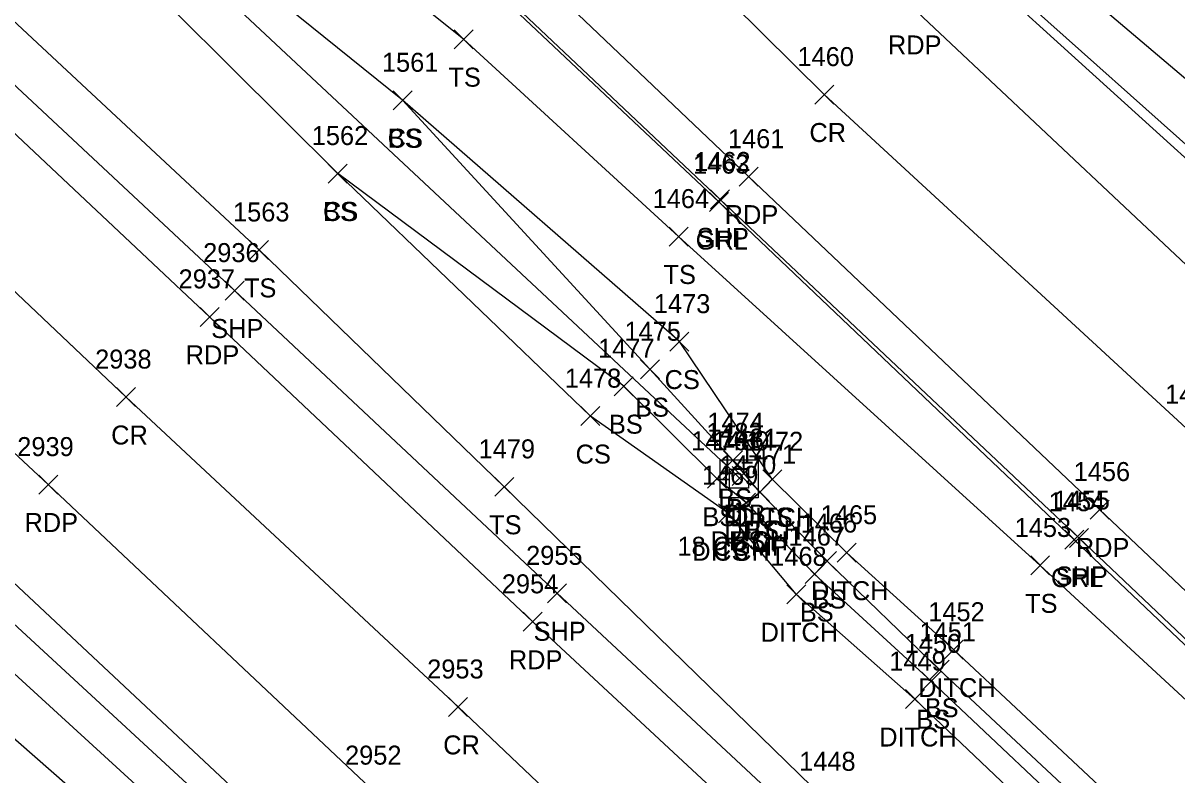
# Model space of a CAD drawing. Extents: x 1647574 to 1652703, y 212895 to 228670.
# Drawn here: x 1649239.7 to 1649361.4, y 226821.7 to 226900.9 of the extents above; entities that cross this region are included whole.
import ezdxf

# ---------------------------------------------------------------- set-up
doc = ezdxf.new("R2010")
doc.units = 0
for name, color, linetype in [('D_A', 7, 'Continuous'), ('D_C', 7, 'Continuous'), ('D_I', 7, 'Continuous'), ('D_TIC', 7, 'Continuous'), ('DCP', 7, 'Continuous'), ('DD', 7, 'Continuous'), ('DS', 7, 'Continuous'), ('L_A', 7, 'Continuous'), ('L_I', 7, 'Continuous'), ('L_TIC', 7, 'Continuous'), ('LELB', 7, 'Continuous'), ('P_A', 7, 'Continuous'), ('P_I', 7, 'Continuous'), ('P_TIC', 7, 'Continuous'), ('PET', 7, 'Continuous'), ('PRC', 7, 'Continuous'), ('PSP', 7, 'Continuous'), ('R_A', 7, 'Continuous'), ('R_I', 7, 'Continuous'), ('R_TIC', 7, 'Continuous'), ('RGR', 7, 'Continuous')]:
    doc.layers.add(name, color=color, linetype=linetype)

msp = doc.modelspace()

# ---------------------------------------------------------------- linework, layer by layer
at = {"layer": 'D_TIC'}
for points in [[(1649313.43, 226852.77), (1649315.43, 226854.77)], [(1649315.43, 226852.77), (1649313.43, 226854.77)], [(1649314.47, 226852.16), (1649316.47, 226854.16)], [(1649316.47, 226852.16), (1649314.47, 226854.16)], [(1649317.71, 226851.83), (1649319.71, 226853.83)], [(1649319.71, 226851.83), (1649317.71, 226853.83)], [(1649317.71, 226851.83), (1649319.71, 226853.83)], [(1649319.71, 226851.83), (1649317.71, 226853.83)], [(1649316.41, 226850.47), (1649318.41, 226852.47)], [(1649318.41, 226850.47), (1649316.41, 226852.47)], [(1649313.05, 226848.25), (1649315.05, 226850.25)], [(1649315.05, 226848.25), (1649313.05, 226850.25)], [(1649314.96, 226849.35), (1649316.96, 226851.35)], [(1649316.96, 226849.35), (1649314.96, 226851.35)], [(1649325.56, 226844.09), (1649327.56, 226846.09)], [(1649327.56, 226844.09), (1649325.56, 226846.09)], [(1649320.24, 226839.71), (1649322.24, 226841.71)], [(1649322.24, 226839.71), (1649320.24, 226841.71)], [(1649336.85, 226833.87), (1649338.85, 226835.87)], [(1649338.85, 226833.87), (1649336.85, 226835.87)], [(1649332.75, 226828.67), (1649334.75, 226830.67)], [(1649334.75, 226828.67), (1649332.75, 226830.67)]]:
    msp.add_lwpolyline(points, dxfattribs=at)
at = {"layer": 'DCP'}
msp.add_lwpolyline([(1649314.43, 226853.77), (1649218.25, 226943.62)], dxfattribs=at)
at = {"layer": 'DD'}
for points in [[(1649433.71, 226734.92), (1649406.56, 226760.63), (1649369.44, 226795.75), (1649333.75, 226829.67), (1649321.24, 226840.71), (1649314.05, 226849.25), (1649315.96, 226850.35), (1649317.41, 226851.47), (1649318.71, 226852.83)], [(1649433.71, 226734.92), (1649435.72, 226737.04), (1649437.39, 226738.45), (1649438.68, 226740.23), (1649411.63, 226765.29), (1649374.97, 226800.14), (1649337.85, 226834.87), (1649326.56, 226845.09), (1649318.71, 226852.83)]]:
    msp.add_lwpolyline(points, dxfattribs=at)
at = {"layer": 'DS'}
for p, q in [((1649313.21, 226854.88), (1649317.21, 226854.88)), ((1649313.21, 226850.88), (1649313.21, 226854.88)), ((1649317.21, 226854.88), (1649317.21, 226850.88)), ((1649314.21, 226851.88), (1649314.21, 226853.88)), ((1649314.21, 226853.88), (1649316.21, 226853.88)), ((1649315.21, 226852.88), (1649315.21, 226852.88)), ((1649315.21, 226852.88), (1649315.21, 226852.88)), ((1649316.21, 226853.88), (1649316.21, 226851.88)), ((1649316.21, 226851.88), (1649314.21, 226851.88)), ((1649317.21, 226850.88), (1649313.21, 226850.88))]:
    msp.add_line(p, q, dxfattribs=at)
at = {"layer": 'L_TIC'}
for points in [[(1649285.16, 226898.19), (1649287.16, 226900.19)], [(1649287.16, 226898.19), (1649285.16, 226900.19)], [(1649278.73, 226891.76), (1649280.73, 226893.76)], [(1649280.73, 226891.76), (1649278.73, 226893.76)], [(1649278.73, 226891.76), (1649280.73, 226893.76)], [(1649280.73, 226891.76), (1649278.73, 226893.76)], [(1649271.9, 226884.04), (1649273.9, 226886.04)], [(1649273.9, 226884.04), (1649271.9, 226886.04)], [(1649271.9, 226884.04), (1649273.9, 226886.04)], [(1649273.9, 226884.04), (1649271.9, 226886.04)], [(1649307.84, 226877.4), (1649309.84, 226879.4)], [(1649309.84, 226877.4), (1649307.84, 226879.4)], [(1649263.6, 226875.99), (1649265.6, 226877.99)], [(1649265.6, 226875.99), (1649263.6, 226877.99)], [(1649307.92, 226866.33), (1649309.92, 226868.33)], [(1649309.92, 226866.33), (1649307.92, 226868.33)], [(1649304.82, 226863.42), (1649306.82, 226865.42)], [(1649306.82, 226863.42), (1649304.82, 226865.42)], [(1649302.05, 226861.63), (1649304.05, 226863.63)], [(1649304.05, 226861.63), (1649302.05, 226863.63)], [(1649298.54, 226858.48), (1649300.54, 226860.48)], [(1649300.54, 226858.48), (1649298.54, 226860.48)], [(1649313.57, 226853.84), (1649315.57, 226855.84)], [(1649315.57, 226853.84), (1649313.57, 226855.84)], [(1649289.45, 226851.03), (1649291.45, 226853.03)], [(1649291.45, 226851.03), (1649289.45, 226853.03)], [(1649311.9, 226851.88), (1649313.9, 226853.88)], [(1649313.9, 226851.88), (1649311.9, 226853.88)], [(1649317.71, 226851.83), (1649319.71, 226853.83)], [(1649319.71, 226851.83), (1649317.71, 226853.83)], [(1649316.41, 226850.47), (1649318.41, 226852.47)], [(1649318.41, 226850.47), (1649316.41, 226852.47)], [(1649313.05, 226848.25), (1649315.05, 226850.25)], [(1649315.05, 226848.25), (1649313.05, 226850.25)], [(1649314.96, 226849.35), (1649316.96, 226851.35)], [(1649316.96, 226849.35), (1649314.96, 226851.35)], [(1649323.5, 226843.21), (1649325.5, 226845.21)], [(1649325.5, 226843.21), (1649323.5, 226845.21)], [(1649345.96, 226842.75), (1649347.96, 226844.75)], [(1649347.96, 226842.75), (1649345.96, 226844.75)], [(1649322.17, 226841.84), (1649324.17, 226843.84)], [(1649324.17, 226841.84), (1649322.17, 226843.84)], [(1649335.35, 226831.76), (1649337.35, 226833.76)], [(1649337.35, 226831.76), (1649335.35, 226833.76)], [(1649334.46, 226830.54), (1649336.46, 226832.54)], [(1649336.46, 226830.54), (1649334.46, 226832.54)]]:
    msp.add_lwpolyline(points, dxfattribs=at)
at = {"layer": 'LELB'}
for points in [[(1649050.36, 227022.26), (1649054.5, 227019.16), (1649077.5, 226992.81), (1649097.35, 226965.43), (1649118.34, 226949.96), (1649138.54, 226931.84), (1649168.25, 226903.68), (1649199.09, 226875.04), (1649233.63, 226842.31), (1649267.99, 226810.62), (1649300.85, 226778.49), (1649342.51, 226739.65), (1649376.73, 226707.3), (1649405.44, 226679.92), (1649436.03, 226650.7), (1649471.83, 226617.33), (1649509.36, 226581.5), (1649541.59, 226550.78), (1649576.43, 226518.4), (1649614.41, 226482.98)], [(1649601.72, 226556.3), (1649565.56, 226590.44), (1649531.93, 226623.52), (1649496.55, 226657.42), (1649463.01, 226688.13), (1649429.09, 226720.61), (1649397.93, 226750.55), (1649357.87, 226787.13), (1649324.24, 226819.11), (1649290.45, 226852.03), (1649264.6, 226876.99), (1649236.49, 226903.17), (1649212.26, 226932.02), (1649172.55, 226966.26), (1649148.69, 226987.13), (1649125.3, 227007.74), (1649116.81, 227012.43), (1649123.68, 227011.79), (1649139.12, 227006.12), (1649163.74, 226998.25), (1649180.85, 226995.42), (1649185.97, 226996.02), (1649188.1, 226997.43)], [(1649611.68, 226660.43), (1649573.8, 226694.76), (1649539.29, 226728.48), (1649506.26, 226759.21), (1649471.69, 226791.64), (1649437.47, 226825.67), (1649400.06, 226860.66), (1649373.97, 226885.13), (1649343.06, 226911.31), (1649307.79, 226942.26), (1649266.92, 226975.01), (1649262.13, 226979.91), (1649252.93, 226990.96)], [(1649593.12, 226613.01), (1649554.76, 226645.44), (1649523.05, 226677.15), (1649485.11, 226713.45), (1649453.02, 226743.38), (1649420.61, 226775.73), (1649384.19, 226809.44), (1649346.96, 226843.75), (1649308.84, 226878.4), (1649286.16, 226899.19), (1649254.43, 226924.59), (1649231.46, 226951.13), (1649215.58, 226955.64), (1649208.66, 226952.13), (1649203.07, 226945.74)], [(1649699.67, 226481.91), (1649679.45, 226501.99), (1649645.41, 226536.66), (1649612.61, 226568.57), (1649578.32, 226600.99), (1649543.98, 226632.95), (1649509.04, 226666.44), (1649473.07, 226698.81), (1649440.27, 226731.3), (1649435.72, 226737.04), (1649408.87, 226762.28), (1649371.65, 226797.42), (1649335.46, 226831.54), (1649323.17, 226842.84), (1649315.96, 226850.35), (1649312.9, 226852.88), (1649303.05, 226862.63), (1649272.9, 226885.04), (1649244.53, 226913.23), (1649219.14, 226937.73), (1649217.77, 226942.22), (1649215.75, 226944.46), (1649217.78, 226946.35), (1649219.53, 226943.85)], [(1649110.63, 226944.12), (1649132.81, 226926.76), (1649161.39, 226897.64), (1649168.83, 226891.36), (1649194.67, 226869.66), (1649227.44, 226835.45), (1649262.79, 226804.48), (1649294.65, 226771.03), (1649336.54, 226732.41), (1649369.74, 226699.93), (1649399.39, 226672.85), (1649429.85, 226642.79), (1649464.73, 226609.99), (1649502.63, 226572.81), (1649535.56, 226543.81), (1649570.19, 226510.51), (1649608.23, 226476.35)], [(1649699.67, 226481.91), (1649706.82, 226489.3), (1649683.4, 226506.92), (1649648.98, 226540.18), (1649615.46, 226571.75), (1649582.54, 226604.31), (1649545.88, 226635.11), (1649514.99, 226670.75), (1649476.91, 226703.47), (1649443.87, 226735.13), (1649437.39, 226738.45), (1649410.25, 226763.49), (1649372.93, 226798.59), (1649336.35, 226832.76), (1649324.5, 226844.21), (1649317.41, 226851.47), (1649314.57, 226854.84), (1649305.82, 226864.42), (1649279.73, 226892.76), (1649248.17, 226918.18), (1649224.51, 226943.02), (1649219.53, 226943.85)], [(1649318.71, 226852.83), (1649308.92, 226867.33), (1649279.73, 226892.76)], [(1649314.05, 226849.25), (1649299.54, 226859.48), (1649272.9, 226885.04)], [(1649196.72, 226872.14), (1649230.92, 226839.54), (1649265.68, 226807.77), (1649297.02, 226774.6), (1649340.28, 226737.1), (1649373.28, 226703.68), (1649402.3, 226677.38), (1649432.52, 226646.6), (1649468.42, 226614.12), (1649504.95, 226574.73), (1649537.46, 226545.9), (1649572.06, 226513.32), (1649610.08, 226478.23)]]:
    msp.add_lwpolyline(points, dxfattribs=at)
at = {"layer": 'P_TIC'}
for points in [[(1649323.19, 226892.36), (1649325.19, 226894.36)], [(1649325.19, 226892.36), (1649323.19, 226894.36)], [(1649315.21, 226883.71), (1649317.21, 226885.71)], [(1649317.21, 226883.71), (1649315.21, 226885.71)], [(1649312.21, 226881.31), (1649314.21, 226883.31)], [(1649314.21, 226881.31), (1649312.21, 226883.31)], [(1649261.03, 226871.71), (1649263.03, 226873.71)], [(1649263.03, 226871.71), (1649261.03, 226873.71)], [(1649258.38, 226868.94), (1649260.38, 226870.94)], [(1649260.38, 226868.94), (1649258.38, 226870.94)], [(1649249.58, 226860.49), (1649251.58, 226862.49)], [(1649251.58, 226860.49), (1649249.58, 226862.49)], [(1649241.38, 226851.27), (1649243.38, 226853.27)], [(1649243.38, 226851.27), (1649241.38, 226853.27)], [(1649352.23, 226848.64), (1649354.23, 226850.64)], [(1649354.23, 226848.64), (1649352.23, 226850.64)], [(1649350.05, 226845.64), (1649352.05, 226847.64)], [(1649352.05, 226845.64), (1649350.05, 226847.64)], [(1649295.02, 226839.81), (1649297.02, 226841.81)], [(1649297.02, 226839.81), (1649295.02, 226841.81)], [(1649292.46, 226836.81), (1649294.46, 226838.81)], [(1649294.46, 226836.81), (1649292.46, 226838.81)], [(1649284.59, 226827.84), (1649286.59, 226829.84)], [(1649286.59, 226827.84), (1649284.59, 226829.84)]]:
    msp.add_lwpolyline(points, dxfattribs=at)
at = {"layer": 'PET'}
for points in [[(1649049.09, 227034.42), (1649086.52, 226998.96), (1649109.21, 226977.52), (1649148.39, 226940.73), (1649176.97, 226913.97), (1649207.9, 226884.37), (1649242.38, 226852.27), (1649276.93, 226819.76), (1649310.57, 226787.99), (1649351.53, 226749.66), (1649386.03, 226717.08), (1649415.53, 226689.26), (1649446.48, 226660.42), (1649481.94, 226626.92), (1649519.05, 226591.95), (1649551.76, 226560.83), (1649585.69, 226528.77), (1649624.3, 226492.34)], [(1649093.95, 227025.5), (1649126.98, 226994.68), (1649165.92, 226958.16), (1649194.97, 226931.06), (1649223.59, 226903.58), (1649259.38, 226869.94), (1649293.46, 226837.81), (1649328.56, 226805.25), (1649367.41, 226768.36), (1649403.39, 226734.5), (1649427.73, 226711.63), (1649463.63, 226677.53), (1649497.38, 226645.66), (1649535.82, 226609.26), (1649568.76, 226578.15), (1649602.84, 226545.72)], [(1649598.45, 226617.55), (1649561.34, 226652.9), (1649529.43, 226682.64), (1649490.94, 226719.16), (1649459.14, 226749.19), (1649424.85, 226781.6), (1649390.38, 226814.48), (1649353.23, 226849.64), (1649316.21, 226884.71), (1649282.4, 226916.91), (1649254.37, 226943.23), (1649236.04, 226960.59), (1649216.52, 226978.85), (1649195.64, 226998.51)], [(1649615.14, 226636.4), (1649578.52, 226671.42), (1649547.96, 226699.81), (1649507.42, 226738.11), (1649475.91, 226767.27), (1649442.1, 226799.89), (1649407.87, 226832.14), (1649370.63, 226867.64), (1649333.42, 226902.59), (1649300.87, 226933.45), (1649271.58, 226961.22), (1649239.83, 226990.77)]]:
    msp.add_lwpolyline(points, dxfattribs=at)
at = {"layer": 'PRC'}
for points in [[(1649071, 227030.27), (1649097.26, 227005.13), (1649118.09, 226986.08), (1649157.01, 226949.33), (1649185.96, 226922.5), (1649216.08, 226894.13), (1649250.58, 226861.49), (1649285.59, 226828.84), (1649319.08, 226797.05), (1649359.19, 226759.47), (1649394.66, 226725.95), (1649419.6, 226702.04), (1649454.56, 226669.33), (1649489.14, 226637.08), (1649527.32, 226600.87), (1649559.91, 226569.96), (1649593.92, 226537.25)], [(1649606.75, 226626.95), (1649570.25, 226661.64), (1649538.47, 226691.38), (1649499.1, 226728.54), (1649467.9, 226758.27), (1649433.88, 226790.68), (1649398.71, 226823.76), (1649362.82, 226857.8), (1649324.19, 226893.36), (1649291.59, 226925.62), (1649262.78, 226952.36), (1649218.05, 226994.51)]]:
    msp.add_lwpolyline(points, dxfattribs=at)
at = {"layer": 'PSP'}
for points in [[(1649099.96, 227024.6), (1649093.95, 227025.5), (1649071, 227030.27), (1649049.09, 227034.42), (1649045.28, 227034.88), (1649054.51, 227026.18), (1649082.27, 226995.84), (1649103.4, 226971.49), (1649121.95, 226952.01), (1649133.13, 226940.72), (1649140.44, 226933.69), (1649170.13, 226906.1), (1649201.41, 226876.98), (1649235.83, 226844.62), (1649270.02, 226812.62), (1649303.26, 226781.03), (1649344.74, 226742.14), (1649379.28, 226709.76), (1649407.94, 226682.37), (1649438.57, 226653.08), (1649474.06, 226619.55), (1649511.81, 226584.21), (1649544.44, 226553.59), (1649578.75, 226520.79)], [(1649099.96, 227024.6), (1649112.12, 227013.19), (1649129.86, 226996.81), (1649168.15, 226960.9), (1649197.39, 226932.91), (1649226.27, 226906.09), (1649262.03, 226872.71), (1649296.02, 226840.81), (1649331.67, 226807.62), (1649370.43, 226771.63), (1649405.77, 226737.7), (1649429.96, 226714.79), (1649466.37, 226680.16), (1649499.94, 226648.68), (1649538.12, 226612.04), (1649571.18, 226581.28), (1649605.62, 226548.46)], [(1649595.64, 226615.02), (1649558.33, 226650.15), (1649527.09, 226680.38), (1649488.24, 226717.06), (1649456.66, 226746.86), (1649422.68, 226779.06), (1649387.28, 226812.32), (1649351.05, 226846.64), (1649313.21, 226882.31), (1649279.73, 226913.94), (1649251.2, 226941.22), (1649233.38, 226957.97), (1649213.56, 226976.76), (1649200.33, 226989.45), (1649199.76, 226990.72), (1649190.94, 226999.11)], [(1649606.95, 226655.87), (1649570.92, 226690.01), (1649534.66, 226724.21), (1649502.87, 226754.78), (1649467.98, 226787.83), (1649433.22, 226820.15), (1649395.45, 226855.86), (1649369.29, 226880.34), (1649338.69, 226908.03), (1649304.51, 226937.47), (1649274.58, 226964.09), (1649261.77, 226975.07), (1649262.11, 226976.25), (1649259.14, 226977.14), (1649257.68, 226977.62), (1649243.4, 226991.01), (1649239.83, 226990.77), (1649218.05, 226994.51), (1649195.64, 226998.51), (1649190.94, 226999.11)]]:
    msp.add_lwpolyline(points, dxfattribs=at)
at = {"layer": 'R_TIC'}
for points in [[(1649312.1, 226881.03), (1649314.1, 226883.03)], [(1649314.1, 226881.03), (1649312.1, 226883.03)], [(1649349.56, 226845.46), (1649351.56, 226847.46)], [(1649351.56, 226845.46), (1649349.56, 226847.46)]]:
    msp.add_lwpolyline(points, dxfattribs=at)
at = {"layer": 'RGR'}
for points in [[(1649553.69, 226650.38), (1649526.88, 226680.04), (1649487.89, 226716.68), (1649456.34, 226746.59), (1649422.28, 226778.82), (1649386.82, 226812.08), (1649350.56, 226846.46), (1649313.1, 226882.03), (1649279.45, 226913.72), (1649250.85, 226941.01), (1649232.6, 226957.18), (1649212.72, 226976.44), (1649200.04, 226988.83)], [(1649607.54, 226656.38), (1649571.29, 226690.65), (1649535.2, 226725), (1649503.13, 226755.54), (1649468.46, 226788.77), (1649433.73, 226820.87), (1649396.03, 226856.51), (1649370.04, 226881.22), (1649339.35, 226908.59), (1649304.93, 226938.03), (1649276.23, 226963.71), (1649262.11, 226976.25)]]:
    msp.add_lwpolyline(points, dxfattribs=at)

# ---------------------------------------------------------------- texts
at = {"layer": 'D_A'}
for s, p in [('P', (1649313.81, 226848.77)), ('DIB', (1649313.57, 226848.16)), ('DI', (1649314.27, 226847.88)), ('DITCH', (1649314.95, 226847.83)), ('DITCH', (1649314.95, 226847.83)), ('DITCH', (1649313.65, 226846.47)), ('DITCH', (1649312.2, 226845.35)), ('DITCH', (1649310.28, 226844.25)), ('DITCH', (1649322.8, 226840.09)), ('DITCH', (1649317.48, 226835.71)), ('DITCH', (1649334.09, 226829.87)), ('DITCH', (1649329.99, 226824.67))]:
    msp.add_text(s, height=2, dxfattribs=at).set_placement(p)
at = {"layer": 'D_C'}
msp.add_text('18 CGMP', height=2, dxfattribs=at).set_placement((1649308.72, 226844.77))
at = {"layer": 'D_I'}
for s, p in [('1482', (1649311.74, 226856.77)), ('1480', (1649312.44, 226855.88)), ('1481', (1649313.34, 226856.16)), ('1472', (1649316.02, 226855.83)), ('1472', (1649316.02, 226855.83)), ('1471', (1649315.28, 226854.47)), ('1470', (1649313.18, 226853.35)), ('1469', (1649311.3, 226852.25)), ('1465', (1649323.82, 226848.09)), ('1468', (1649318.5, 226843.71)), ('1452', (1649335.16, 226837.87)), ('1449', (1649331.05, 226832.67))]:
    msp.add_text(s, height=2, dxfattribs=at).set_placement(p)
at = {"layer": 'L_A'}
for s, p in [('TS', (1649284.57, 226894.19)), ('CS', (1649278.17, 226887.76)), ('BS', (1649278.17, 226887.76)), ('CS', (1649271.35, 226880.04)), ('BS', (1649271.35, 226880.04)), ('TS', (1649307.25, 226873.4)), ('TS', (1649263.01, 226871.99)), ('CS', (1649307.36, 226862.33)), ('BS', (1649304.26, 226859.42)), ('BS', (1649301.49, 226857.63)), ('CS', (1649297.98, 226854.48)), ('BS', (1649313.01, 226849.84)), ('TS', (1649288.86, 226847.03)), ('BS', (1649311.34, 226847.88)), ('CS', (1649317.15, 226847.83)), ('BS', (1649315.85, 226846.47)), ('BS', (1649314.4, 226845.35)), ('CS', (1649312.49, 226844.25)), ('BS', (1649322.94, 226839.21)), ('TS', (1649345.37, 226838.75)), ('BS', (1649321.62, 226837.84)), ('BS', (1649334.79, 226827.76)), ('BS', (1649333.9, 226826.54))]:
    msp.add_text(s, height=2, dxfattribs=at).set_placement(p)
at = {"layer": 'L_I'}
for s, p in [('1561', (1649277.56, 226895.76)), ('1561', (1649277.56, 226895.76)), ('1562', (1649270.16, 226888.04)), ('1562', (1649270.16, 226888.04)), ('1464', (1649306.1, 226881.4)), ('1563', (1649261.86, 226879.99)), ('1473', (1649306.23, 226870.33)), ('1475', (1649303.13, 226867.42)), ('1477', (1649300.35, 226865.63)), ('1478', (1649296.84, 226862.48)), ('1474', (1649311.87, 226857.84)), ('1476', (1649310.16, 226855.88)), ('1472', (1649316.02, 226855.83)), ('1479', (1649287.75, 226855.03)), ('1471', (1649315.28, 226854.47)), ('1470', (1649313.18, 226853.35)), ('1469', (1649311.3, 226852.25)), ('1466', (1649321.7, 226847.21)), ('1467', (1649320.43, 226845.84)), ('1453', (1649344.27, 226846.75)), ('1451', (1649334.23, 226835.76)), ('1450', (1649332.68, 226834.54)), ('1448', (1649321.55, 226822.11))]:
    msp.add_text(s, height=2, dxfattribs=at).set_placement(p)
at = {"layer": 'P_A'}
for s, p in [('RDP', (1649330.91, 226897.59)), ('CR', (1649322.63, 226888.36)), ('RDP', (1649313.7, 226879.71)), ('SHP', (1649310.75, 226877.31)), ('SHP', (1649259.56, 226867.71)), ('RDP', (1649256.87, 226864.94)), ('CR', (1649249.01, 226856.49)), ('RDP', (1649239.87, 226847.27)), ('RDP', (1649350.72, 226844.64)), ('SHP', (1649348.59, 226841.64)), ('SHP', (1649293.55, 226835.81)), ('RDP', (1649290.94, 226832.81)), ('CR', (1649284.02, 226823.84))]:
    msp.add_text(s, height=2, dxfattribs=at).set_placement(p)
at = {"layer": 'P_I'}
for s, p in [('1460', (1649321.37, 226896.36)), ('1461', (1649314.04, 226887.71)), ('1462', (1649310.47, 226885.31)), ('2936', (1649258.71, 226875.71)), ('2937', (1649256.12, 226872.94)), ('2938', (1649247.32, 226864.49)), ('1457', (1649360.13, 226860.8)), ('2939', (1649239.11, 226855.27)), ('1456', (1649350.49, 226852.64)), ('1455', (1649348.36, 226849.64)), ('2955', (1649292.76, 226843.81)), ('2954', (1649290.2, 226840.81)), ('2953', (1649282.33, 226831.84)), ('2952', (1649273.67, 226822.76))]:
    msp.add_text(s, height=2, dxfattribs=at).set_placement(p)
at = {"layer": 'R_A'}
for p in [(1649310.64, 226877.03), (1649348.1, 226841.46)]:
    msp.add_text('GRL', height=2, dxfattribs=at).set_placement(p)
at = {"layer": 'R_I'}
for s, p in [('1463', (1649310.36, 226885.03)), ('1454', (1649347.86, 226849.46))]:
    msp.add_text(s, height=2, dxfattribs=at).set_placement(p)

doc.saveas('drawing.dxf')
